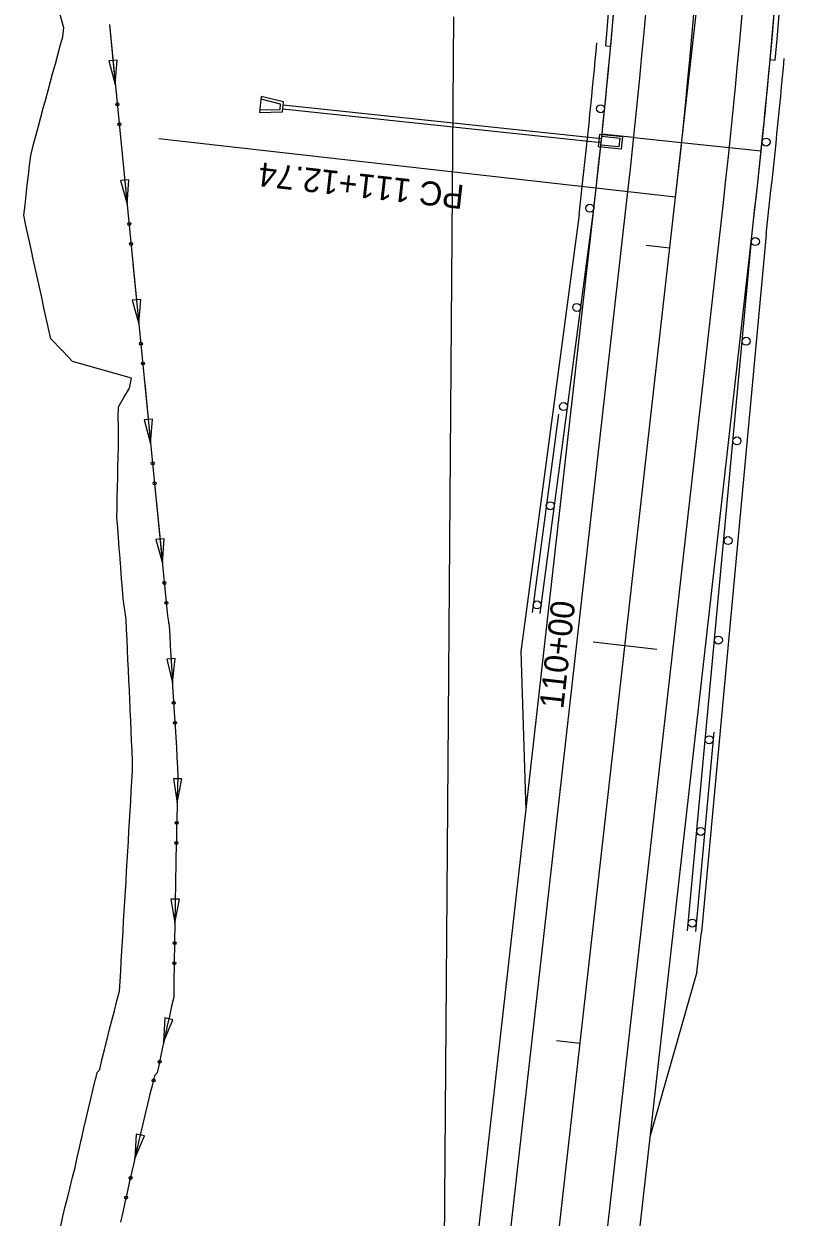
# Model space of a CAD drawing. Extents: x 1311167 to 1314552, y 2087587 to 2090602.
# Drawn here: x 1313889.7 to 1314084.9, y 2088855.3 to 2089153.5 of the extents above; entities that cross this region are included whole.
import ezdxf

# ---------------------------------------------------------------- set-up
doc = ezdxf.new("R2010")
doc.units = 0
for name, color, linetype in [('MOT_Proposed Road_2', 7, 'Continuous'), ('R_Bridge', 7, 'Continuous'), ('R_Guardrail', 7, 'Continuous'), ('R_Horz Alg Annot_Side Road', 7, 'Continuous'), ('R_Horz Alg Stationing', 7, 'Continuous'), ('R_Proposed Road', 7, 'Continuous'), ('R_Special Ditch', 7, 'Continuous'), ('S_EDGE_BITUMINOUS', 7, 'Continuous'), ('S_EDGE_CONCRETE', 7, 'Continuous'), ('S_EDGE_PAVEMENT', 7, 'Continuous'), ('S_PAVEMENT_CROWN', 7, 'Continuous')]:
    doc.layers.add(name, color=color, linetype=linetype)

msp = doc.modelspace()

# ---------------------------------------------------------------- linework, layer by layer
at = {"layer": 'MOT_Proposed Road_2'}
for p, q in [((1314031.89, 2089105.33), (1314032.69, 2089112.44)), ((1314071.68, 2089101.2), (1314072.4, 2089107.54)), ((1314055.54, 2088926.91), (1314071.68, 2089101.2)), ((1314062.14, 2088976.48), (1314057.52, 2088926.68))]:
    msp.add_line(p, q, dxfattribs=at)
for points in [[(1314018.67, 2089006.19), (1314031.89, 2089105.33)], [(1314023.28, 2089055.99), (1314016.67, 2089006.42)]]:
    msp.add_lwpolyline(points, dxfattribs=at)
for centre in [(1314033.81, 2089132.25), (1314075.17, 2089123.93), (1314031.12, 2089107.41), (1314072.49, 2089099.07), (1314027.86, 2089082.63), (1314070.18, 2089074.17), (1314024.55, 2089057.85), (1314067.88, 2089049.28), (1314021.24, 2089033.07), (1314065.68, 2089024.38), (1314017.94, 2089008.28), (1314063.26, 2088999.49), (1314060.96, 2088974.6), (1314058.84, 2088951.69), (1314056.72, 2088928.79)]:
    msp.add_circle(centre, 1, dxfattribs=at)
for centre, radius, end in [((1312300.74, 2089307.86), 1742.95, 354.75197), ((1312300.69, 2089307.45), 1782.95, 354.7766)]:
    msp.add_arc(centre, radius, 353.5625, end, dxfattribs=at)
at = {"layer": 'R_Bridge'}
for points in [[(1314045.18, 2089098.21), (1314051.14, 2089097.54)], [(1314031.98, 2088999.06), (1314047.88, 2088997.27)], [(1314022.75, 2088899.47), (1314028.72, 2088898.8)]]:
    msp.add_lwpolyline(points, dxfattribs=at)
at = {"layer": 'R_Guardrail'}
msp.add_line((1314033.89, 2089123.16), (1314034.11, 2089125.38), dxfattribs=at)
for points in [[(1314052.57, 2089110.2), (1314073.23, 2089293.36), (1314055.57, 2089476.83)], [(1314052.57, 2089110.2), (1313923.39, 2089124.77)]]:
    msp.add_lwpolyline(points, dxfattribs=at)
at = {"layer": 'R_Horz Alg Annot_Side Road'}
for p, q in [((1314028.42, 2089105.73), (1314029.22, 2089112.83)), ((1314075.16, 2089100.8), (1314075.87, 2089107.15)), ((1314028.42, 2089105.8), (1314015.19, 2089006.58)), ((1314075.17, 2089100.87), (1314059.02, 2088926.55)), ((1314015.19, 2089006.58), (1314013.87, 2088996.67)), ((1314057.89, 2088916.58), (1314059.02, 2088926.55)), ((1314057.89, 2088916.58), (1314046.23, 2088875.63))]:
    msp.add_line(p, q, dxfattribs=at)
msp.add_lwpolyline([(1314013.87, 2088996.67), (1314015.16, 2088957)], dxfattribs=at)
for centre, radius, end in [((1312300.74, 2089307.86), 1739.45, 354.75197), ((1312300.69, 2089307.45), 1786.45, 354.77698)]:
    msp.add_arc(centre, radius, 353.5625, end, dxfattribs=at)
at = {"layer": 'R_Horz Alg Stationing'}
msp.add_line((1313988.32, 2088000.7), (1313997.14, 2089155.24), dxfattribs=at)
at = {"layer": 'R_Proposed Road'}
msp.add_line((1314001.16, 2088654.58), (1314052.57, 2089110.2), dxfattribs=at)
msp.add_line((1314001.16, 2088654.58), (1314052.57, 2089110.2), dxfattribs=at)
msp.add_line((1314001.16, 2088654.58), (1314052.57, 2089110.2), dxfattribs=at)
msp.add_arc((1312300.74, 2089307.86), 1762.95, 353.5625, 5.5, dxfattribs=at)
msp.add_arc((1312300.74, 2089307.86), 1762.95, 353.5625, 5.5, dxfattribs=at)
at = {"layer": 'R_Special Ditch'}
for p, q in [((1314035.08, 2089147.96), (1314036.32, 2089147.85)), ((1314076.19, 2089144.52), (1314077.43, 2089144.41))]:
    msp.add_line(p, q, dxfattribs=at)
for radius, start, end in [(1782.95, 354.7437, 5.46314), (1784.2, 354.74371, 5.46313), (1741.7, 354.73258, 5.47425), (1742.95, 354.73258, 5.47426)]:
    msp.add_arc((1312300.74, 2089307.86), radius, start, end, dxfattribs=at)
at = {"layer": 'S_EDGE_BITUMINOUS'}
for p, q in [((1313912.99, 2089144.4), (1313910.88, 2089144.2)), ((1313910.88, 2089144.2), (1313912.52, 2089138.33)), ((1313912.52, 2089138.33), (1313912.99, 2089144.4)), ((1313949.01, 2089135.28), (1313948.59, 2089131.3)), ((1313954.57, 2089133.94), (1313949.01, 2089135.28)), ((1313954.3, 2089131.45), (1313954.57, 2089133.94)), ((1313948.59, 2089131.3), (1313954.3, 2089131.45)), ((1313954.38, 2089132.21), (1314033.95, 2089123.78)), ((1313954.49, 2089133.21), (1314034.05, 2089124.78)), ((1313915.93, 2089114.51), (1313913.82, 2089114.3)), ((1313913.82, 2089114.3), (1313915.46, 2089108.43)), ((1313915.46, 2089108.43), (1313915.93, 2089114.51)), ((1313918.87, 2089084.62), (1313916.76, 2089084.41)), ((1313916.76, 2089084.41), (1313918.4, 2089078.54)), ((1313918.4, 2089078.54), (1313918.87, 2089084.62)), ((1313921.81, 2089054.72), (1313919.7, 2089054.51)), ((1313919.7, 2089054.51), (1313921.34, 2089048.65)), ((1313921.34, 2089048.65), (1313921.81, 2089054.72)), ((1313924.75, 2089024.83), (1313922.64, 2089024.62)), ((1313922.64, 2089024.62), (1313924.29, 2089018.75)), ((1313924.29, 2089018.75), (1313924.75, 2089024.83)), ((1313927.5, 2088994.89), (1313925.39, 2088994.76)), ((1313925.39, 2088994.76), (1313926.8, 2088988.83)), ((1313926.8, 2088988.83), (1313927.5, 2088994.89)), ((1313929.19, 2088964.81), (1313927.07, 2088964.86)), ((1313927.07, 2088964.86), (1313927.98, 2088958.84)), ((1313927.98, 2088958.84), (1313929.19, 2088964.81)), ((1313928.54, 2088934.79), (1313926.43, 2088934.82)), ((1313926.43, 2088934.82), (1313927.38, 2088928.81)), ((1313927.38, 2088928.81), (1313928.54, 2088934.79)), ((1313924.87, 2088905.14), (1313924.61, 2088899.05)), ((1313924.61, 2088899.05), (1313926.94, 2088904.68)), ((1313926.94, 2088904.68), (1313924.87, 2088905.14)), ((1313917.72, 2088876.11), (1313917.4, 2088870.02)), ((1313917.4, 2088870.02), (1313919.78, 2088875.63)), ((1313919.78, 2088875.63), (1313917.72, 2088876.11))]:
    msp.add_line(p, q, dxfattribs=at)
for points in [[(1313911.06, 2089153.26), (1313913.81, 2089125.19), (1313925.58, 2089005.56), (1313925.98, 2089003.04), (1313926.12, 2089000.61), (1313926.26, 2088998.07), (1313926.41, 2088995.54), (1313926.55, 2088993.01), (1313926.7, 2088990.47), (1313926.85, 2088987.94), (1313927, 2088985.4), (1313927.15, 2088982.87), (1313927.24, 2088981.42), (1313927.31, 2088980.34), (1313927.46, 2088977.8), (1313927.62, 2088975.27), (1313927.78, 2088972.73), (1313927.94, 2088970.2), (1313928.1, 2088967.71), (1313928.14, 2088965.28), (1313928.08, 2088962.81), (1313928.02, 2088960.3), (1313927.96, 2088957.79), (1313927.9, 2088955.28), (1313927.84, 2088952.77), (1313927.79, 2088950.26), (1313927.74, 2088947.75), (1313927.68, 2088945.23), (1313927.63, 2088942.72), (1313927.58, 2088940.21), (1313927.54, 2088937.7), (1313927.49, 2088935.19), (1313927.45, 2088932.67), (1313927.41, 2088930.16), (1313927.37, 2088927.65), (1313927.33, 2088925.14), (1313927.29, 2088922.62), (1313927.25, 2088920.11), (1313927.22, 2088917.6), (1313927.19, 2088915.08), (1313927.15, 2088912.57), (1313927.13, 2088910.27), (1313926.61, 2088908.03), (1313926.06, 2088905.57), (1313925.51, 2088903.11), (1313924.96, 2088900.65), (1313924.48, 2088898.43), (1313924.43, 2088898.19), (1313923.9, 2088895.73), (1313923.37, 2088893.27), (1313922.97, 2088891.37), (1313922.33, 2088890.69), (1313921.9, 2088888.97), (1313921.78, 2088888.48), (1313921.18, 2088886.03), (1313920.59, 2088883.57), (1313920, 2088881.12), (1313919.41, 2088878.67), (1313918.83, 2088876.21), (1313918.26, 2088873.76), (1313918.14, 2088873.26), (1313917.69, 2088871.3), (1313917.13, 2088868.84), (1313916.57, 2088866.39), (1313916.02, 2088863.93), (1313915.47, 2088861.47), (1313914.92, 2088859.02), (1313914.38, 2088856.56), (1313913.84, 2088854.1)], [(1313911.06, 2089153.26), (1313912.52, 2089138.33)], [(1313948.66, 2089131.97), (1313953.7, 2089132.1), (1313953.84, 2089133.43), (1313948.94, 2089134.61)], [(1313913.99, 2089123.4), (1313913.99, 2089123.36)], [(1313913.99, 2089123.36), (1313915.46, 2089108.43)], [(1313916.93, 2089093.51), (1313916.93, 2089093.47)], [(1313916.93, 2089093.47), (1313918.4, 2089078.54)], [(1313919.87, 2089063.61), (1313919.88, 2089063.58)], [(1313919.88, 2089063.57), (1313921.34, 2089048.65)], [(1313922.81, 2089033.72), (1313922.82, 2089033.68)], [(1313922.82, 2089033.68), (1313924.29, 2089018.75)], [(1313925.86, 2089003.84), (1313925.86, 2089003.8)], [(1313925.86, 2089003.8), (1313925.98, 2089003.04), (1313926.12, 2089000.61), (1313926.26, 2088998.07), (1313926.41, 2088995.54), (1313926.55, 2088993.01), (1313926.7, 2088990.47), (1313926.8, 2088988.83)], [(1313927.71, 2088973.86), (1313927.71, 2088973.82)], [(1313927.71, 2088973.82), (1313927.78, 2088972.73), (1313927.94, 2088970.2), (1313928.1, 2088967.71), (1313928.14, 2088965.28), (1313928.08, 2088962.81), (1313928.02, 2088960.3), (1313927.98, 2088958.84)], [(1313927.66, 2088943.8), (1313927.63, 2088942.72), (1313927.58, 2088940.21), (1313927.54, 2088937.7), (1313927.49, 2088935.19), (1313927.45, 2088932.67), (1313927.41, 2088930.16), (1313927.38, 2088928.81)], [(1313927.66, 2088943.84), (1313927.66, 2088943.8)], [(1313927.17, 2088913.77), (1313927.15, 2088912.57), (1313927.13, 2088910.27), (1313926.61, 2088908.03), (1313926.06, 2088905.57), (1313925.51, 2088903.11), (1313924.96, 2088900.65), (1313924.61, 2088899.05)], [(1313927.17, 2088913.81), (1313927.17, 2088913.77)], [(1313920.84, 2088884.62), (1313920.59, 2088883.57), (1313920, 2088881.12), (1313919.41, 2088878.67), (1313918.83, 2088876.21), (1313918.26, 2088873.76), (1313918.14, 2088873.26), (1313917.69, 2088871.3), (1313917.4, 2088870.02)], [(1313920.85, 2088884.66), (1313920.84, 2088884.62)], [(1313914.12, 2088855.38), (1313914.12, 2088855.35)]]:
    msp.add_lwpolyline(points, dxfattribs=at)
for points in [[(1314033.32, 2089122.72), (1314033.66, 2089125.93), (1314039.3, 2089125.34), (1314038.96, 2089122.13)], [(1314033.87, 2089123.17), (1314034.11, 2089125.38), (1314038.58, 2089124.91), (1314038.35, 2089122.7)]]:
    msp.add_lwpolyline(points, close=True, dxfattribs=at)
for centre in [(1313913.05, 2089133.35), (1313913.54, 2089128.36), (1313915.99, 2089103.46), (1313916.48, 2089098.47), (1313918.93, 2089073.56), (1313919.42, 2089068.58), (1313921.87, 2089043.67), (1313922.36, 2089038.68), (1313924.81, 2089013.77), (1313925.3, 2089008.79), (1313927.13, 2088983.84), (1313927.44, 2088978.84), (1313927.9, 2088953.83), (1313927.79, 2088948.82), (1313927.34, 2088923.8), (1313927.27, 2088918.79), (1313923.6, 2088894.15), (1313922.07, 2088889.49), (1313916.33, 2088865.13), (1313915.23, 2088860.24)]:
    msp.add_circle(centre, 0.375, dxfattribs=at)
at = {"layer": 'S_EDGE_CONCRETE'}
for points in [[(1313915.23, 2089004.69), (1313914.49, 2089009.8), (1313914.29, 2089012.34), (1313914.1, 2089014.88), (1313913.91, 2089017.42), (1313913.87, 2089018.02), (1313913.84, 2089018.37), (1313913.72, 2089019.95), (1313913.53, 2089022.49), (1313913.33, 2089025.03), (1313913.12, 2089027.57), (1313912.92, 2089030.11), (1313912.95, 2089032.62), (1313913.01, 2089035.13), (1313913.08, 2089037.64), (1313913.14, 2089040.15), (1313913.18, 2089042.66), (1313913.23, 2089045.17), (1313913.32, 2089047.67), (1313913.35, 2089050.19), (1313913.29, 2089052.71), (1313913.23, 2089055.23), (1313913.32, 2089057.74), (1313914.62, 2089060.11), (1313916.07, 2089062.46), (1313916.56, 2089064.92), (1313901.85, 2089069.09), (1313900.83, 2089070.16), (1313899.15, 2089071.92), (1313896.44, 2089074.74), (1313895.82, 2089077.32), (1313895.25, 2089079.9), (1313894.68, 2089082.48), (1313894.12, 2089085.06), (1313893.55, 2089087.64), (1313892.99, 2089090.22), (1313892.42, 2089092.8), (1313891.85, 2089095.38), (1313891.72, 2089095.99), (1313891.29, 2089097.96), (1313890.72, 2089100.54), (1313890.16, 2089103.12), (1313889.67, 2089105.69), (1313889.96, 2089108.17), (1313890.25, 2089110.66), (1313890.53, 2089113.14), (1313890.82, 2089115.62), (1313891.11, 2089118.11), (1313891.4, 2089120.59), (1313891.96, 2089123.04), (1313892.63, 2089125.48), (1313893.29, 2089127.93), (1313893.91, 2089130.17), (1313894.51, 2089132.39), (1313895.12, 2089134.61), (1313895.73, 2089136.83), (1313896.34, 2089139.05), (1313896.94, 2089141.28), (1313897.55, 2089143.5), (1313898.16, 2089145.73), (1313898.77, 2089147.96), (1313899.38, 2089150.18), (1313899.63, 2089152.45), (1313897.83, 2089159.07)], [(1313898.95, 2088853.06), (1313899.41, 2088855.52), (1313900.02, 2088857.97), (1313900.63, 2088860.42), (1313901.24, 2088862.86), (1313901.86, 2088865.31), (1313902.47, 2088867.76), (1313903.01, 2088870.21), (1313903.57, 2088872.66), (1313904.01, 2088874.63), (1313904.13, 2088875.12), (1313904.69, 2088877.57), (1313905.26, 2088880.02), (1313905.83, 2088882.47), (1313906.41, 2088884.92), (1313906.99, 2088887.37), (1313907.58, 2088889.82), (1313907.7, 2088890.31), (1313907.99, 2088891.52), (1313908.64, 2088892.22), (1313909.18, 2088894.67), (1313909.79, 2088897.12), (1313910.41, 2088899.57), (1313910.47, 2088899.8), (1313911.03, 2088902.01), (1313911.66, 2088904.46), (1313912.29, 2088906.9), (1313912.93, 2088909.35), (1313913.58, 2088911.79), (1313913.72, 2088914.29), (1313913.87, 2088916.79), (1313914.03, 2088919.29), (1313914.17, 2088921.79), (1313914.31, 2088924.28), (1313914.45, 2088926.78), (1313914.6, 2088929.28), (1313914.75, 2088931.78), (1313914.9, 2088934.28), (1313915.04, 2088936.78), (1313915.2, 2088939.28), (1313915.36, 2088941.78), (1313915.51, 2088944.28), (1313915.65, 2088946.78), (1313915.79, 2088949.28), (1313915.94, 2088951.78), (1313916.08, 2088954.28), (1313916.23, 2088956.78), (1313916.37, 2088959.27), (1313916.52, 2088961.77), (1313916.67, 2088964.27), (1313916.82, 2088966.77), (1313916.81, 2088969.29), (1313916.71, 2088971.82), (1313916.6, 2088974.34), (1313916.5, 2088976.87), (1313916.4, 2088979.4), (1313916.27, 2088981.93), (1313916.22, 2088983.01), (1313916.15, 2088984.46), (1313916.04, 2088986.99), (1313915.92, 2088989.52), (1313915.81, 2088992.04), (1313915.68, 2088994.57), (1313915.56, 2088997.1), (1313915.45, 2088999.63), (1313915.34, 2089002.16), (1313915.23, 2089004.69)]]:
    msp.add_lwpolyline(points, dxfattribs=at)
at = {"layer": 'S_EDGE_PAVEMENT'}
for p, q in [((1313981.29, 2088656.82), (1314032.69, 2089112.44)), ((1314021.03, 2088652.34), (1314072.44, 2089107.95))]:
    msp.add_line(p, q, dxfattribs=at)
for radius in [1782.95, 1742.95]:
    msp.add_arc((1312300.74, 2089307.86), radius, 353.5625, 5.5, dxfattribs=at)
at = {"layer": 'S_PAVEMENT_CROWN'}
for p, q in [((1314042.11, 2089125.04), (1314034.16, 2089125.88)), ((1314042.11, 2089125.04), (1314065.98, 2089122.54)), ((1314065.98, 2089122.54), (1314073.94, 2089121.7)), ((1313989.24, 2088655.92), (1314040.64, 2089111.54)), ((1313989.24, 2088655.92), (1314040.64, 2089111.54)), ((1314013.09, 2088653.23), (1314064.49, 2089108.85)), ((1314013.09, 2088653.23), (1314064.49, 2089108.85))]:
    msp.add_line(p, q, dxfattribs=at)
for radius in [1774.95, 1774.95, 1750.95, 1750.95]:
    msp.add_arc((1312300.74, 2089307.86), radius, 353.5625, 5.5, dxfattribs=at)

# ---------------------------------------------------------------- texts
at = {"layer": 'R_Bridge'}
msp.add_text('110+00', height=6, rotation=83.5625, dxfattribs=at).set_placement((1314024.47, 2088982.15))
at = {"layer": 'R_Guardrail'}
msp.add_text('PC 111+12.74', height=6, rotation=173.5625, dxfattribs=at).set_placement((1313999.94, 2089113.12))

doc.saveas('drawing.dxf')
